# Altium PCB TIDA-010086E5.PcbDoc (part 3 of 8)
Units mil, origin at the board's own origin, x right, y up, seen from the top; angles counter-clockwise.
Board outline 6400 x 6200 mil, 6 copper layers (Top Layer, Power, AGND, Signal, PGND, Bottom Layer), stack 70.536 mil thick; 717 components, 376 nets, 2259 pads, 2183 vias.
Unrouted connection lines stored in the file: 1424.
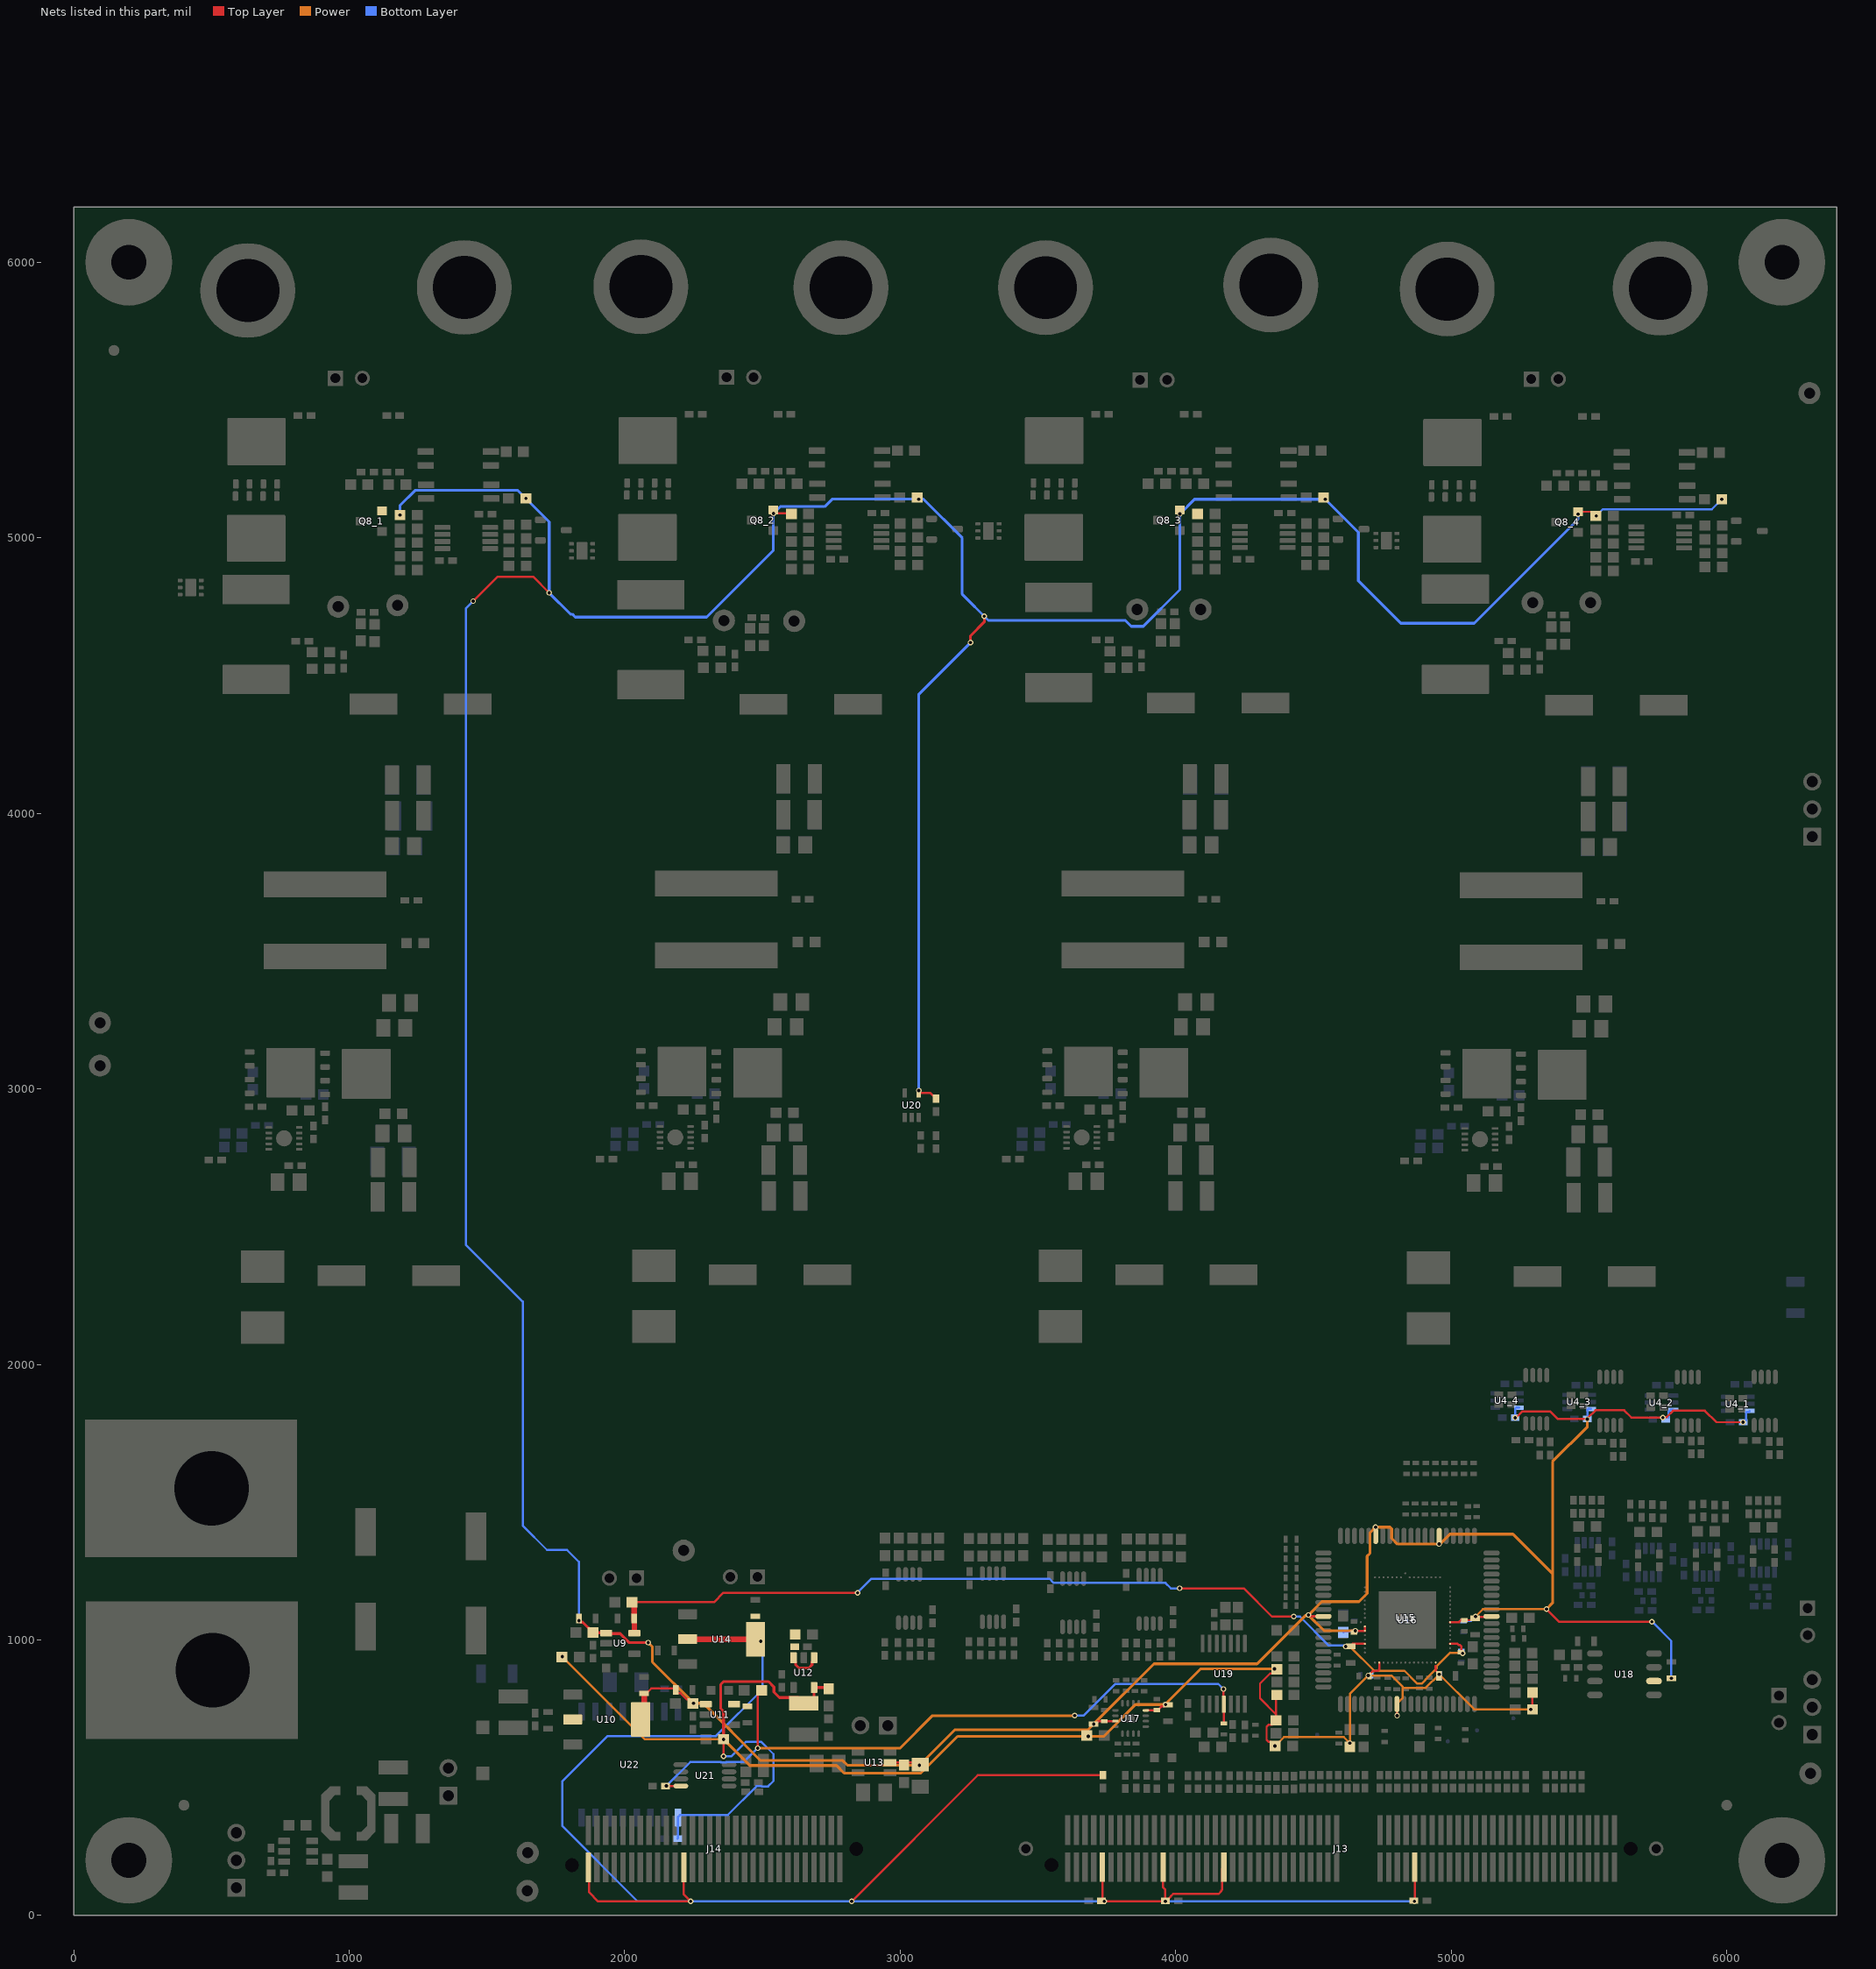
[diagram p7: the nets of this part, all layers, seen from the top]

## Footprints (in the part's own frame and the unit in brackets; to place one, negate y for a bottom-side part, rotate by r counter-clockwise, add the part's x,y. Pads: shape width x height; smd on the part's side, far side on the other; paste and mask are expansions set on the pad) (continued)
RSK0064B-MFG [mm] "Recommended Land Pattern"
  round 0.18 smd paste-1000 mask+0: 1(-3.925,3) 2(-3.925,2.6) 3(-3.925,2.2) 4(-3.935,1.8) 5(-3.935,1.4) 6(-3.925,1) 7(-3.935,0.6) 8(-3.925,0.2) 9(-4.3,-0.2) 10(-3.925,-0.6) 11(-3.925,-1) 12(-3.925,-1.4) 13(-3.925,-1.8) 14(-3.925,-2.2) 15(-3.925,-2.6) 16(-3.925,-3) 17(-3,-3.925) 18(-2.6,-3.925) 19(-2.2,-3.925) 20(-1.8,-3.935) 21(-1.4,-3.935) 22(-1,-3.925) 23(-0.6,-3.935) 24(-0.2,-3.925) 25(0.2,-4.3) 26(0.6,-3.925) 27(1,-3.925) 28(1.4,-3.925) 29(1.8,-3.925) 30(2.2,-3.925) 31(2.6,-3.925) 32(3,-3.925) 33(3.925,-3) 34(3.925,-2.6) 35(3.925,-2.2) 36(3.935,-1.8) 37(3.935,-1.4) 38(3.925,-1) 39(3.935,-0.6) 40(3.925,-0.2) 41(3.935,0.2) 42(3.925,0.6) 43(3.925,1) 44(3.925,1.4) 45(3.925,1.8) 46(3.925,2.2) 47(3.925,2.6) 48(3.925,3) 49(3,3.925) 50(2.6,3.925) 51(2.2,3.925) 52(1.8,3.935) 53(1.4,3.935) 54(1,3.925) 55(0.6,3.935) 56(0.2,3.925) 57(-0.2,3.935) 58(-0.6,3.925) 59(-1,3.925) 60(-1.4,3.925) 61(-1.8,3.925) 62(-2.2,3.925) 63(-2.6,3.925) 64(-3,3.925)
  rrect2% 5.31x5.31 smd paste-1000 mask+0: 65(0,0)
  Top Layer region: -2.9,4.4 -2.9,3.55 -2.913,3.5 -2.95,3.463 -3,3.45 -3,3.45 -3.038,3.458 -3.071,3.479 -3.092,3.512 -3.1,3.55 -3.1,3.55 -3.1,4.4
  Top Layer region: -2.5,4.4 -2.5,3.55 -2.508,3.512 -2.529,3.479 -2.562,3.458 -2.6,3.45 -2.6,3.45 -2.638,3.458 -2.671,3.479 -2.692,3.512 -2.7,3.55 -2.7,3.55 -2.7,4.4
  Top Layer region: -2.1,4.4 -2.1,3.55 -2.113,3.5 -2.15,3.463 -2.2,3.45 -2.2,3.45 -2.238,3.458 -2.271,3.479 -2.292,3.512 -2.3,3.55 -2.3,3.55 -2.3,4.4
  Top Layer region: -1.7,4.4 -1.7,3.55 -1.713,3.5 -1.75,3.463 -1.8,3.45 -1.8,3.45 -1.838,3.458 -1.871,3.479 -1.892,3.512 -1.9,3.55 -1.9,3.55 -1.9,4.4
  Top Layer region: -1.3,4.4 -1.3,3.55 -1.313,3.5 -1.35,3.463 -1.4,3.45 -1.4,3.45 -1.438,3.458 -1.471,3.479 -1.492,3.512 -1.5,3.55 -1.5,3.55 -1.5,4.4
  Top Layer region: -0.9,4.4 -0.9,3.55 -0.908,3.512 -0.929,3.479 -0.962,3.458 -1,3.45 -1,3.45 -1.038,3.458 -1.071,3.479 -1.092,3.512 -1.1,3.55 -1.1,3.55 -1.1,4.4
  Top Layer region: -0.5,4.4 -0.5,3.55 -0.513,3.5 -0.55,3.463 -0.6,3.45 -0.6,3.45 -0.638,3.458 -0.671,3.479 -0.692,3.512 -0.7,3.55 -0.7,3.55 -0.7,4.4
  Top Layer region: -0.1,4.4 -0.1,3.55 -0.108,3.512 -0.129,3.479 -0.162,3.458 -0.2,3.45 -0.2,3.45 -0.238,3.458 -0.271,3.479 -0.292,3.512 -0.3,3.55 -0.3,3.55 -0.3,4.4
  Top Layer region: 0.3,4.4 0.3,3.55 0.292,3.512 0.271,3.479 0.238,3.458 0.2,3.45 0.2,3.45 0.162,3.458 0.129,3.479 0.108,3.512 0.1,3.55 0.1,3.55 0.1,4.4
  Top Layer region: 0.7,4.4 0.7,3.55 0.687,3.5 0.65,3.463 0.6,3.45 0.6,3.45 0.562,3.458 0.529,3.479 0.508,3.512 0.5,3.55 0.5,3.55 0.5,4.4
  Top Layer region: 1.1,4.4 1.1,3.55 1.087,3.5 1.05,3.463 1,3.45 1,3.45 0.962,3.458 0.929,3.479 0.908,3.512 0.9,3.55 0.9,3.55 0.9,4.4
  Top Layer region: 1.5,4.4 1.5,3.55 1.487,3.5 1.45,3.463 1.4,3.45 1.4,3.45 1.362,3.458 1.329,3.479 1.308,3.512 1.3,3.55 1.3,3.55 1.3,4.4
  Top Layer region: 1.9,4.4 1.9,3.55 1.887,3.5 1.85,3.463 1.8,3.45 1.8,3.45 1.762,3.458 1.729,3.479 1.708,3.512 1.7,3.55 1.7,3.55 1.7,4.4
  Top Layer region: 2.3,4.4 2.3,3.55 2.287,3.5 2.25,3.463 2.2,3.45 2.2,3.45 2.162,3.458 2.129,3.479 2.108,3.512 2.1,3.55 2.1,3.55 2.1,4.4
  Top Layer region: 2.7,4.4 2.7,3.55 2.692,3.512 2.671,3.479 2.638,3.458 2.6,3.45 2.6,3.45 2.562,3.458 2.529,3.479 2.508,3.512 2.5,3.55 2.5,3.55 2.5,4.4
  Top Layer region: 3.1,4.4 3.1,3.55 3.087,3.5 3.05,3.463 3,3.45 3,3.45 2.962,3.458 2.929,3.479 2.908,3.512 2.9,3.55 2.9,3.55 2.9,4.4
  Top Layer region: 2.9,-4.4 2.9,-3.55 2.908,-3.512 2.929,-3.479 2.962,-3.458 3,-3.45 3,-3.45 3.038,-3.458 3.071,-3.479 3.092,-3.512 3.1,-3.55 3.1,-3.55 3.1,-4.4
  Top Layer region: 2.5,-4.4 2.5,-3.55 2.508,-3.512 2.529,-3.479 2.562,-3.458 2.6,-3.45 2.6,-3.45 2.638,-3.458 2.671,-3.479 2.692,-3.512 2.7,-3.55 2.7,-3.55 2.7,-4.4
  Top Layer region: 2.1,-4.4 2.1,-3.55 2.108,-3.512 2.129,-3.479 2.162,-3.458 2.2,-3.45 2.2,-3.45 2.238,-3.458 2.271,-3.479 2.292,-3.512 2.3,-3.55 2.3,-3.55 2.3,-4.4
  Top Layer region: 1.7,-4.4 1.7,-3.55 1.708,-3.512 1.729,-3.479 1.762,-3.458 1.8,-3.45 1.8,-3.45 1.838,-3.458 1.871,-3.479 1.892,-3.512 1.9,-3.55 1.9,-3.55 1.9,-4.4
  Top Layer region: 1.3,-4.4 1.3,-3.55 1.308,-3.512 1.329,-3.479 1.362,-3.458 1.4,-3.45 1.4,-3.45 1.438,-3.458 1.471,-3.479 1.492,-3.512 1.5,-3.55 1.5,-3.55 1.5,-4.4
  Top Layer region: 0.9,-4.4 0.9,-3.55 0.908,-3.512 0.929,-3.479 0.962,-3.458 1,-3.45 1,-3.45 1.038,-3.458 1.071,-3.479 1.092,-3.512 1.1,-3.55 1.1,-3.55 1.1,-4.4
  Top Layer region: 0.5,-4.4 0.5,-3.55 0.508,-3.512 0.529,-3.479 0.562,-3.458 0.6,-3.45 0.6,-3.45 0.638,-3.458 0.671,-3.479 0.692,-3.512 0.7,-3.55 0.7,-3.55 0.7,-4.4
  Top Layer region: 0.1,-4.4 0.1,-3.55 0.108,-3.512 0.129,-3.479 0.162,-3.458 0.2,-3.45 0.2,-3.45 0.238,-3.458 0.271,-3.479 0.292,-3.512 0.3,-3.55 0.3,-3.55 0.3,-4.4
  Top Layer region: -0.3,-4.4 -0.3,-3.55 -0.292,-3.512 -0.271,-3.479 -0.238,-3.458 -0.2,-3.45 -0.2,-3.45 -0.162,-3.458 -0.129,-3.479 -0.108,-3.512 -0.1,-3.55 -0.1,-3.55 -0.1,-4.4
  Top Layer region: -0.7,-4.4 -0.7,-3.55 -0.692,-3.512 -0.671,-3.479 -0.638,-3.458 -0.6,-3.45 -0.6,-3.45 -0.562,-3.458 -0.529,-3.479 -0.508,-3.512 -0.5,-3.55 -0.5,-3.55 -0.5,-4.4
  Top Layer region: -1.1,-4.4 -1.1,-3.55 -1.092,-3.512 -1.071,-3.479 -1.038,-3.458 -1,-3.45 -1,-3.45 -0.962,-3.458 -0.929,-3.479 -0.908,-3.512 -0.9,-3.55 -0.9,-3.55 -0.9,-4.4
  Top Layer region: -1.5,-4.4 -1.5,-3.55 -1.492,-3.512 -1.471,-3.479 -1.438,-3.458 -1.4,-3.45 -1.4,-3.45 -1.362,-3.458 -1.329,-3.479 -1.308,-3.512 -1.3,-3.55 -1.3,-3.55 -1.3,-4.4
  Top Layer region: -1.9,-4.4 -1.9,-3.55 -1.892,-3.512 -1.871,-3.479 -1.838,-3.458 -1.8,-3.45 -1.8,-3.45 -1.762,-3.458 -1.729,-3.479 -1.708,-3.512 -1.7,-3.55 -1.7,-3.55 -1.7,-4.4
  Top Layer region: -2.3,-4.4 -2.3,-3.55 -2.292,-3.512 -2.271,-3.479 -2.238,-3.458 -2.2,-3.45 -2.2,-3.45 -2.162,-3.458 -2.129,-3.479 -2.108,-3.512 -2.1,-3.55 -2.1,-3.55 -2.1,-4.4
  Top Layer region: -2.7,-4.4 -2.7,-3.55 -2.692,-3.512 -2.671,-3.479 -2.638,-3.458 -2.6,-3.45 -2.6,-3.45 -2.562,-3.458 -2.529,-3.479 -2.508,-3.512 -2.5,-3.55 -2.5,-3.55 -2.5,-4.4
  Top Layer region: -3.1,-4.4 -3.1,-3.55 -3.092,-3.512 -3.071,-3.479 -3.038,-3.458 -3,-3.45 -3,-3.45 -2.962,-3.458 -2.929,-3.479 -2.908,-3.512 -2.9,-3.55 -2.9,-3.55 -2.9,-4.4
  Top Layer region: 4.4,2.9 3.55,2.9 3.512,2.908 3.479,2.929 3.458,2.962 3.45,3 3.45,3 3.458,3.038 3.479,3.071 3.512,3.092 3.55,3.1 3.55,3.1 4.4,3.1
  Top Layer region: 4.4,2.5 3.55,2.5 3.512,2.508 3.479,2.529 3.458,2.562 3.45,2.6 3.45,2.6 3.458,2.638 3.479,2.671 3.512,2.692 3.55,2.7 3.55,2.7 4.4,2.7
  Top Layer region: 4.4,2.1 3.55,2.1 3.512,2.108 3.479,2.129 3.458,2.162 3.45,2.2 3.45,2.2 3.458,2.238 3.479,2.271 3.512,2.292 3.55,2.3 3.55,2.3 4.4,2.3
  Top Layer region: 4.4,1.7 3.55,1.7 3.512,1.708 3.479,1.729 3.458,1.762 3.45,1.8 3.45,1.8 3.458,1.838 3.479,1.871 3.512,1.892 3.55,1.9 3.55,1.9 4.4,1.9
  Top Layer region: 4.4,1.3 3.55,1.3 3.512,1.308 3.479,1.329 3.458,1.362 3.45,1.4 3.45,1.4 3.458,1.438 3.479,1.471 3.512,1.492 3.55,1.5 3.55,1.5 4.4,1.5
  Top Layer region: 4.4,0.9 3.55,0.9 3.512,0.908 3.479,0.929 3.458,0.962 3.45,1 3.45,1 3.458,1.038 3.479,1.071 3.512,1.092 3.55,1.1 3.55,1.1 4.4,1.1
  Top Layer region: 4.4,0.5 3.55,0.5 3.512,0.508 3.479,0.529 3.458,0.562 3.45,0.6 3.45,0.6 3.458,0.638 3.479,0.671 3.512,0.692 3.55,0.7 3.55,0.7 4.4,0.7
  Top Layer region: 4.4,0.1 3.55,0.1 3.512,0.108 3.479,0.129 3.458,0.162 3.45,0.2 3.45,0.2 3.458,0.238 3.479,0.271 3.512,0.292 3.55,0.3 3.55,0.3 4.4,0.3
  Top Layer region: 4.4,-0.3 3.55,-0.3 3.512,-0.292 3.479,-0.271 3.458,-0.238 3.45,-0.2 3.45,-0.2 3.458,-0.162 3.479,-0.129 3.512,-0.108 3.55,-0.1 3.55,-0.1 4.4,-0.1
  Top Layer region: 4.4,-0.7 3.55,-0.7 3.512,-0.692 3.479,-0.671 3.458,-0.638 3.45,-0.6 3.45,-0.6 3.458,-0.562 3.479,-0.529 3.512,-0.508 3.55,-0.5 3.55,-0.5 4.4,-0.5
  Top Layer region: 4.4,-1.1 3.55,-1.1 3.512,-1.092 3.479,-1.071 3.458,-1.038 3.45,-1 3.45,-1 3.458,-0.962 3.479,-0.929 3.512,-0.908 3.55,-0.9 3.55,-0.9 4.4,-0.9
  Top Layer region: 4.4,-1.5 3.55,-1.5 3.512,-1.492 3.479,-1.471 3.458,-1.438 3.45,-1.4 3.45,-1.4 3.458,-1.362 3.479,-1.329 3.512,-1.308 3.55,-1.3 3.55,-1.3 4.4,-1.3
  Top Layer region: 4.4,-1.9 3.55,-1.9 3.512,-1.892 3.479,-1.871 3.458,-1.838 3.45,-1.8 3.45,-1.8 3.458,-1.762 3.479,-1.729 3.512,-1.708 3.55,-1.7 3.55,-1.7 4.4,-1.7
  Top Layer region: 4.4,-2.3 3.55,-2.3 3.512,-2.292 3.479,-2.271 3.458,-2.238 3.45,-2.2 3.45,-2.2 3.458,-2.162 3.479,-2.129 3.512,-2.108 3.55,-2.1 3.55,-2.1 4.4,-2.1
  Top Layer region: 4.4,-2.7 3.55,-2.7 3.512,-2.692 3.479,-2.671 3.458,-2.638 3.45,-2.6 3.45,-2.6 3.458,-2.562 3.479,-2.529 3.512,-2.508 3.55,-2.5 3.55,-2.5 4.4,-2.5
  Top Layer region: 4.4,-3.1 3.55,-3.1 3.512,-3.092 3.479,-3.071 3.458,-3.038 3.45,-3 3.45,-3 3.458,-2.962 3.479,-2.929 3.512,-2.908 3.55,-2.9 3.55,-2.9 4.4,-2.9
  Top Layer region: -4.4,-2.9 -3.55,-2.9 -3.512,-2.908 -3.479,-2.929 -3.458,-2.962 -3.45,-3 -3.45,-3 -3.463,-3.05 -3.5,-3.087 -3.55,-3.1 -3.55,-3.1 -4.4,-3.1
  Top Layer region: -4.4,-2.5 -3.55,-2.5 -3.512,-2.508 -3.479,-2.529 -3.458,-2.562 -3.45,-2.6 -3.45,-2.6 -3.458,-2.638 -3.479,-2.671 -3.512,-2.692 -3.55,-2.7 -3.55,-2.7 -4.4,-2.7
  Top Layer region: -4.4,-2.1 -3.55,-2.1 -3.512,-2.108 -3.479,-2.129 -3.458,-2.162 -3.45,-2.2 -3.45,-2.2 -3.458,-2.238 -3.479,-2.271 -3.512,-2.292 -3.55,-2.3 -3.55,-2.3 -4.4,-2.3
  Top Layer region: -4.4,-1.7 -3.55,-1.7 -3.512,-1.708 -3.479,-1.729 -3.458,-1.762 -3.45,-1.8 -3.45,-1.8 -3.463,-1.85 -3.5,-1.887 -3.55,-1.9 -3.55,-1.9 -4.4,-1.9
  Top Layer region: -4.4,-1.3 -3.55,-1.3 -3.512,-1.308 -3.479,-1.329 -3.458,-1.362 -3.45,-1.4 -3.45,-1.4 -3.458,-1.438 -3.479,-1.471 -3.512,-1.492 -3.55,-1.5 -3.55,-1.5 -4.4,-1.5
  Top Layer region: -4.4,-0.9 -3.55,-0.9 -3.512,-0.908 -3.479,-0.929 -3.458,-0.962 -3.45,-1 -3.45,-1 -3.458,-1.038 -3.479,-1.071 -3.512,-1.092 -3.55,-1.1 -3.55,-1.1 -4.4,-1.1
  Top Layer region: -4.4,-0.5 -3.55,-0.5 -3.512,-0.508 -3.479,-0.529 -3.458,-0.562 -3.45,-0.6 -3.45,-0.6 -3.458,-0.638 -3.479,-0.671 -3.512,-0.692 -3.55,-0.7 -3.55,-0.7 -4.4,-0.7
  Top Layer region: -4.4,-0.1 -3.55,-0.1 -3.512,-0.108 -3.479,-0.129 -3.458,-0.162 -3.45,-0.2 -3.45,-0.2 -3.458,-0.238 -3.479,-0.271 -3.512,-0.292 -3.55,-0.3 -3.55,-0.3 -4.4,-0.3
  Top Layer region: -4.4,0.3 -3.55,0.3 -3.512,0.292 -3.479,0.271 -3.458,0.238 -3.45,0.2 -3.45,0.2 -3.458,0.162 -3.479,0.129 -3.512,0.108 -3.55,0.1 -3.55,0.1 -4.4,0.1
  Top Layer region: -4.4,0.7 -3.55,0.7 -3.512,0.692 -3.479,0.671 -3.458,0.638 -3.45,0.6 -3.45,0.6 -3.458,0.562 -3.479,0.529 -3.512,0.508 -3.55,0.5 -3.55,0.5 -4.4,0.5
  Top Layer region: -4.4,1.1 -3.55,1.1 -3.512,1.092 -3.479,1.071 -3.458,1.038 -3.45,1 -3.45,1 -3.458,0.962 -3.479,0.929 -3.512,0.908 -3.55,0.9 -3.55,0.9 -4.4,0.9
  Top Layer region: -4.4,1.5 -3.55,1.5 -3.512,1.492 -3.479,1.471 -3.458,1.438 -3.45,1.4 -3.45,1.4 -3.458,1.362 -3.479,1.329 -3.512,1.308 -3.55,1.3 -3.55,1.3 -4.4,1.3
  Top Layer region: -4.4,1.9 -3.55,1.9 -3.512,1.892 -3.479,1.871 -3.458,1.838 -3.45,1.8 -3.45,1.8 -3.458,1.762 -3.479,1.729 -3.512,1.708 -3.55,1.7 -3.55,1.7 -4.4,1.7
  Top Layer region: -4.4,2.3 -3.55,2.3 -3.512,2.292 -3.479,2.271 -3.458,2.238 -3.45,2.2 -3.45,2.2 -3.463,2.15 -3.5,2.113 -3.55,2.1 -3.55,2.1 -4.4,2.1
  Top Layer region: -4.4,2.7 -3.55,2.7 -3.512,2.692 -3.479,2.671 -3.458,2.638 -3.45,2.6 -3.45,2.6 -3.463,2.55 -3.5,2.513 -3.55,2.5 -3.55,2.5 -4.4,2.5
  Top Layer region: -4.4,3.1 -3.55,3.1 -3.512,3.092 -3.479,3.071 -3.458,3.038 -3.45,3 -3.45,3 -3.463,2.95 -3.5,2.913 -3.55,2.9 -3.55,2.9 -4.4,2.9
  silkscreen extent -4.62,-4.08 4.08,4.08, body extent -4.5,-4.5 4.5,4.5, height 0.25
RTE0016D [mm] "QFN, 16-Leads, Body 3x3mm, Pitch 0.5mm"
  oval 0.6x0.24 smd: 1(-1.4,0.75) 2(-1.4,0.25) 3(-1.4,-0.25) 4(-1.4,-0.75) 9(1.4,-0.75) 10(1.4,-0.25) 11(1.4,0.25) 12(1.4,0.75)
  oval 0.24x0.6 smd: 5(-0.75,-1.4) 6(-0.25,-1.4) 7(0.25,-1.4) 8(0.75,-1.4) 13(0.75,1.4) 14(0.25,1.4) 15(-0.25,1.4) 16(-0.75,1.4)
  rect 0.8x0.8 smd paste-0.85: 17(0,0)
  silkscreen extent -1.72,-1.73 1.72,1.73, body extent -1.57,-1.57 1.58,1.58, height 0.81
Samtec_HTSW-102-07-G-S [mm] "Samtec 100mil, 1x2, 230 mil above insulator"
  rrect6% 1.65x1.65 hole 1.016: 1(-1.27,0)
  round 1.65 hole 1.016: 2(1.27,0)
  silkscreen extent -3.3,-1.27 2.54,1.27, body extent -2.54,-1.27 2.54,1.27, height 8.38
Samtec_HTSW-103-07-G-S [mm] "Samtec 100mil, 1x3, 230 mil above insulator"
  rrect6% 1.65x1.65 hole 1.016: 1(-2.54,0)
  round 1.65 hole 1.016: 2(0,0) 3(2.54,0)
  silkscreen extent -4.57,-1.27 3.81,1.27, body extent -3.81,-1.27 3.81,1.27, height 8.38
SOT-23 [mm] "SOT23, 3-Leads, Body 2.9x1.3mm, Pitch 0.95mm, Lead Span 2.5mm, IPC Medium Density"
  rrect50% 1x0.6 smd: 1(-1.2,0.95) 2(-1.2,-0.95) 3(1.2,0)
  silkscreen extent -1.62,-1.5 0.7,1.5, body extent -1.16,-1.45 1.21,1.45, height 1
TI_Stacked_Overlay_Small [mil]
  silkscreen extent -418,-98 418,98
TP_SM_1MM [mil] "1mm Test Point, SMT"
  round 15 smd paste-19.68: 1(0,0)
WEEE_Minimum [mil] "WEEElie bin"
  silkscreen extent -95,-172 99,104
WL-SMCW_GREEN [mm] "WURTH"
  rect 0.8x0.8 smd: 1(-0.8,0) 2(0.8,0)
  silkscreen extent -1.9,-0.8 1.2,0.8, body extent -0.85,-0.45 0.85,0.45, height 0.8
Wurth_60900213421 [mil] "Shunt, 2.54mm, Black"
  round 1 on Mech3: 0(0,0)
  body extent -98,-48 98,48, height 338
XAL1010 [mm] "COILCRAFT"
  rect 2.38x11.31 smd: 1(-3.325,0) 2(3.325,0)
  silkscreen extent -5.3,-6 5.3,6, body extent -5.25,-5.9 5.25,5.9, height 10

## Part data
C1 C2 C9_1 C9_2 C9_3 C9_4 C10_1 C10_2 C10_3 C10_4: library part CMP-0012120-3, "CAP ALUM POLY 150UF 20% 50V SMD", Cap_Case=F12, Manufacturer=Panasonic, Tolerance_%=20%, Value1="0.024 ohm", Value2=50, ValueDisplayed=150uF
C3_1 C3_2 C3_3 C3_4 C4_1 C4_2 C4_3 C4_4 C12_1 C12_2 C12_3 C12_4 C18_1 C18_2 C18_3 C18_4 C41 C42 C43 C48 C59: library part CMP-0085817-1, "CAP, CERM, 22 µF, 35 V,+/- 20%, X5R, 1210", Cap_Case=1210, Manufacturer="Taiyo Yuden", TempCo=X5R, Tolerance_%=20%, Value2=35V, ValueDisplayed=22µF
C5_1 C5_2 C5_3 C5_4 C7_1 C7_2 C7_3 C7_4 C13_1 C13_2 C13_3 C13_4 C15_1 C15_2 C15_3 C15_4 C57 C62 C63: library part CMP-0008350-2, "CAP, CERM, 1 uF, 50 V, +/- 10%, X7R, 0805", Cap_Case=0805, Manufacturer=MuRata, Supplier Part Number 1=490-4736-1-ND, TempCo=X7R, Tolerance_%=10%, Value1=Unknown, Value2=50V, ValueDisplayed=1uF
C6_1 C6_2 C6_3 C6_4 C14_1 C14_2 C14_3 C14_4 C40 C44: library part CMP-0007469-4, "CAP, CERM, 0.1 uF, 100 V, +/- 10%, X7R, 0603", Cap_Case=0603, Manufacturer=MuRata, Supplier Part Number 1=490-3285-1-ND, TempCo=X7R, Tolerance_%=10%, Value1=Unknown, Value2=100V, ValueDisplayed=0.1uF
C8_1 C8_2 C8_3 C8_4 C11_1 C11_2 C11_3 C11_4 C16_1 C16_2 C16_3 C16_4 C17_1 C17_2 C17_3 C17_4: library part CMP-0009201-2, "CAP, CERM, 47 uF, 16 V, +/- 20%, X6S, 1210", Cap_Case=1210, Manufacturer=MuRata, Supplier Part Number 1=490-9968-1-ND, TempCo=X6S, Tolerance_%=20%, Value1=Unknown, Value2=16V, ValueDisplayed=47uF
C19_1 C19_2 C19_3 C19_4: library part CMP-0008093-2, "CAP, CERM, 100 pF, 100 V, +/- 5%, C0G/NP0, 0805", Cap_Case=0805, Manufacturer=MuRata, Supplier Part Number 1=490-1599-1-ND, TempCo=C0G/NP0, Tolerance_%=5%, Value1=Unknown, Value2=100V, ValueDisplayed=100pF
C20_1 C20_2 C20_3 C20_4 C61 C102: library part CMP-0006644-2, "CAP, CERM, 0.015 uF, 16 V, +/- 10%, X7R, 0402", Cap_Case=0402, Manufacturer=MuRata, Supplier Part Number 1=490-1314-1-ND, TempCo=X7R, Tolerance_%=10%, Value1=Unknown, Value2=16V, ValueDisplayed=0.015uF
C21_1 C21_2 C21_3 C21_4: library part CMP-0008309-2, "CAP, CERM, 4.7 uF, 50 V, +/- 10%, X5R, 0805", Cap_Case=0805, Manufacturer=MuRata, Supplier Part Number 1=GRM21BR61H475KE51L-ND, TempCo=X5R, Tolerance_%=10%, Value1=Unknown, Value2=50V, ValueDisplayed=4.7uF
C22_1 C22_2 C22_3 C22_4 C23_1 C23_2 C23_3 C23_4 C25_1 C25_2 C25_3 C25_4 C26_1 C26_2 C26_3 C26_4 C27_1 C27_2 C27_3 C27_4 C29_1 C29_2 C29_3 C29_4 C30_1 C30_2 C30_3 C30_4 C33_1 C33_2 C33_3 C33_4 C34_1 C34_2 C34_3 C34_4 C36_1 C36_2 C36_3 C36_4 C38_1 C38_2 C38_3 C38_4 C39_1 C39_2 C39_3 C39_4 C45 C53 C54 C56 C64 C65 C69 C70 C71 C72 C75 C76 C83 C84 C89 C92 C99 C100 C101 C103 C104 C105 C106 C107_1 C107_2 C107_3 C107_4: library part CMP-0006591-2, "CAP, CERM, 0.1 uF, 16 V, +/- 10%, X5R, 0402", Cap_Case=0402, Manufacturer=MuRata, Supplier Part Number 1=490-5415-1-ND, TempCo=X5R, Tolerance_%=10%, Value1=Unknown, Value2=16V, ValueDisplayed=0.1uF
C24_1 C24_2 C24_3 C24_4: library part CMP-0007445-4, "CAP, CERM, 0.22 uF, 50 V, +/- 10%, X7R, 0603", Cap_Case=0603, Manufacturer=MuRata, Supplier Part Number 1=490-12546-1-ND, TempCo=X7R, Tolerance_%=10%, Value1=Unknown, Value2=50V, ValueDisplayed=0.22uF
C28_1 C28_2 C28_3 C28_4 C32_1 C32_2 C32_3 C32_4: library part CMP-0006412-2, "CAP, CERM, 1000 pF, 50 V, +/- 5%, C0G/NP0, 0402", Cap_Case=0402, Manufacturer=MuRata, Supplier Part Number 1=490-3244-1-ND, TempCo=C0G/NP0, Tolerance_%=5%, Value1=Unknown, Value2=50V, ValueDisplayed=1000pF
C31_1 C31_2 C31_3 C31_4: library part CMP-0007210-4, "CAP, CERM, 3300 pF, 50 V, +/- 5%, C0G/NP0, 0603", Cap_Case=0603, Manufacturer=MuRata, Supplier Part Number 1=GRM1885C1H332JA01D-ND, TempCo=C0G/NP0, Tolerance_%=5%, Value1=Unknown, Value2=50V, ValueDisplayed=3300pF
C35_1 C35_2 C35_3 C35_4: library part CMP-0006611-2, "CAP, CERM, 4700 pF, 25 V, +/- 10%, X5R, 0402", Cap_Case=0402, Manufacturer=MuRata, Supplier Part Number 1=GRM155R61E472KA01D-ND, TempCo=X5R, Tolerance_%=10%, Value1=Unknown, Value2=25V, ValueDisplayed=4700pF
C37_1 C37_2 C37_3 C37_4: library part CMP-0007479-4, "CAP, CERM, 3300 pF, 100 V, +/- 10%, X7R, 0603", Cap_Case=0603, Manufacturer=MuRata, Supplier Part Number 1=490-1481-1-ND, TempCo=X7R, Tolerance_%=10%, Value1=Unknown, Value2=100V, ValueDisplayed=3300pF
C46 C47 C50 C51 C52 C60 C66 C68 C73 C74 C82 C85 C86 C87: library part CMP-0076705-3, "CAP, CERM, 1 µF, 25 V,+/- 10%, X7R, AEC-Q200 Grade 1, 0603", Cap_Case=1.6x0.8x0.8mm, Manufacturer=TDK, Supplier Part Number 1=445-6931-1-ND, TempCo=X7R, Tolerance_%=10%, Value2=25V, ValueDisplayed=1µF
C49 C58: library part CMP-0076705-3, "CAP TANT POLY 2.2UF 10V 0603", Cap_Case=1.6x0.8x0.8mm, Manufacturer="KYOCERA AVX", TempCo=X7R, Tolerance_%=20%, Value2=10V, ValueDisplayed=2.2uF
C55 C67 C77 C80 C81 C90: library part CMP-0007344-5, "CAP, CERM, 10 uF, 25 V, +/- 20%, X5R, 0603", Cap_Case=0603, Manufacturer=MuRata, Supplier Part Number 1=490-7202-1-ND, TempCo=X5R, Tolerance_%=20%, Value1=Unknown, Value2=25V, ValueDisplayed=10uF
C78 C79: library part CMP-0064936-4, "CAP, CERM, 4.7 uF, 16 V,+/- 10%, X7R, 0603", Cap_Case=0603, Manufacturer=MuRata, TempCo=X7R, Tolerance_%=10%, Value1=Unknown, Value2=16V, ValueDisplayed=4.7uF
C88 C91 C108_1 C108_2 C108_3 C108_4: library part CMP-0006640-1, "CAP, CERM, 0.1 uF, 16 V, +/- 5%, X7R, 0402", Cap_Case=0402, Manufacturer=MuRata, Supplier Part Number 1=490-6327-1-ND, TempCo=X7R, Tolerance_%=5%, Value1=Unknown, Value2=16V, ValueDisplayed=0.1uF
C93: library part CMP-0078265-1, "CAP, CERM, 0.22 µF, 16 V,+/- 10%, X7R, AEC-Q200 Grade 1, 0402", Cap_Case=0402, Manufacturer=MuRata, Supplier Part Number 1=490-10671-1-ND, TempCo=X7R, Tolerance_%=10%, Value2=16V, ValueDisplayed=0.22µF
C94 C95 C96 C97 C98: library part CMP-0006639-2, "CAP, CERM, 0.01 uF, 16 V, +/- 10%, X7R, 0402", Cap_Case=0402, Manufacturer=MuRata, Supplier Part Number 1=490-1313-1-ND, TempCo=X7R, Tolerance_%=10%, Value1=Unknown, Value2=16V, ValueDisplayed=0.01uF
D1 D2 D3 D4: library part CMP-0002894-2, "LED, Green, SMD", Color=green, Manufacturer="Wurth Elektronik", Value1=W, Value2=2V
F1_1 F1_2 F1_3 F1_4: library part CMP-0003569-2, "Fuse, 15 A, SMD", Irating_A=15A
FID1 FID2 FID3: library part CMP-0077181-1, "Fiducial mark.  There is nothing to buy or mount.", Manufacturer=N/A
H1 H2 H3 H4: library part CMP-0003617-1, "Machine Screw, Round, #4-40 x 1/4, Nylon, Philips panhead", Manufacturer="B&F Fastener Supply", Supplier Part Number 1=H542-ND
H5 H6 H7 H8: library part CMP-0003610-1, "Standoff, Hex, 0.5\"L #4-40 Nylon", Manufacturer=Keystone, Supplier Part Number 1=36-1902C-ND
J1 J2: library part CMP-0055387-2, "Standard Banana Jack, Uninsulated, 15A", Manufacturer="Cinch Connectivity", Supplier Part Number 1=J147-ND
J3 J4 J8_1 J8_2 J8_3 J8_4 J15 J16: library part CMP-0075228-1, "Header (Shrouded), 2.5mm, 2x1, Tin, TH", Color=White, Current_A=3A, Manufacturer="JST Manufacturing", Supplier Part Number 1=455-1611-ND, Voltage_V=250V
J5 J6 J11: library part CMP-0075484-1, "Header, 100mil, 3x1, Gold, TH", Manufacturer=Samtec, Supplier Part Number 1=HTSW-103-07-G-S-ND
J7_1 J7_2 J7_3 J7_4 J9_1 J9_2 J9_3 J9_4: library part CMP-0001389-1, "Terminal Connector Rectangular Lug, Grounding 6-14 AWG 3/16 Stud", Digikey Part Number=298-11610-ND, Manufacturer=Panduit, Mouser Part Number=644-CXS35-36T-C, Operating Temperature Range=to, Voltage_V=600V
J10 J12: library part CMP-0075483-1, "Header, 100mil, 2x1, Gold, TH", Manufacturer=Samtec, Supplier Part Number 1=SAM8736-ND
J13: library part CMP-0003814-2, "C2000 controlCARD-120HSEC connector, SMT", Manufacturer=Samtec
J14: library part CMP-0003859-2, "C2000 controlCARD-180HSEC (60-pin addon) connector, SMT", Manufacturer=Samtec
L1_1 L1_2 L1_3 L1_4: library part CMP-0060950-1, "Inductor, Shielded, Composite, 4.7 uH, 24 A, 0.01 ohm, SMD", Manufacturer=Coilcraft, Supplier Part Number 1=994-XAL1010-472MEB, Value1="0.01 ohm", Value2=24A, ValueDisplayed=4.7uH
L2: library part CMP-0061372-2, "Inductor, Shielded Drum Core, Ferrite, 18 uH, 0.8 A, 0.55 ohm, SMD", Manufacturer=Coilcraft, Value1="0.55 ohm", Value2=0.8A, ValueDisplayed=18uH
L3: library part CMP-0003369-1, "Ferrite Bead, 1000 ohm @ 100 MHz, 1.5 A, 1806", Manufacturer=MuRata, Supplier Part Number 1=490-1061-1-ND, Value1="0.09 ohm", Value2=1.5A, ValueDisplayed="1000 ohm"
LBL1: library part CMP-0003625-1, "Thermal Transfer Printable Labels, 0.650\" W x 0.200\" H - 10,000 per roll", Manufacturer=Brady, Supplier Part Number 1=97C5133
Logo1: library part CMP-0074844-1
Logo2: library part CMP-0074838-1, "Texas Instrument Corporate Signature"
Logo3: library part CMP-0074847-1, "FCC_disclaimer"
Logo4: library part CMP-0074769-3, Manufacturer="Texas Instruments"
Logo5 Logo6: library part CMP-0074837-2, "IEC 61010-1 Hot Surface Warning", Manufacturer="Texas Instruments"
Q1_1 Q1_2 Q1_3 Q1_4 Q4_1 Q4_2 Q4_3 Q4_4: library part CMP-0000572-1, "MOSFET, N-CH, 30 V, 100 A, DQJ0008A (VSONP-8)", Alternate Manufacturer=None, Manufacturer="Texas Instruments", Supplier Part Number 1=296-28437-1-ND, Value1=0, Value2="13.2 nC"
Q2_1 Q2_2 Q2_3 Q2_4 Q3_1 Q3_2 Q3_3 Q3_4: library part CMP-0000586-2, "MOSFET, N-CH, 30 V, 100 A, DNK0008A (VSON-CLIP-8)", Alternate Manufacturer=None, Manufacturer="Texas Instruments", Supplier Part Number 1=CSD17573Q5B-ND, Value1=0.0014, Value2="49 nC"
Q5_1 Q5_2 Q5_3 Q5_4 Q7_1 Q7_2 Q7_3 Q7_4: library part CMP-0120549-1, "3.75-kVRMS, Single-Channel Opto-Emulator with Analog Transistor Output", Emiiter Collector Voltage=7V, Forward Current=5mA, Manufacturer="Texas Instruments", Operating Temperature Range="-55°C to +125°C", Power_TotalModule=200mW, Voltage_Isolation_Vrms=3750Vrms
Q6_1 Q6_2 Q6_3 Q6_4: library part CMP-0085603-1, "MOSFET, N-CH, 60 V, 0.115 A, AEC-Q101, SOT-23", Alternate Manufacturer=None, Manufacturer="Diodes Inc.", Value1="? ohm", Value2="0.223 nC"
Q8_1 Q8_2 Q8_3 Q8_4: library part CMP-0090761-1, "P-Channel 50V 130mA (Ta) 225mW (Ta) Surface Mount SOT-23-3 (TO-236)", Digikey Part Number=BSS84LT1GOSCT-ND, Drain To Source Breakdown Voltage=-50V, Input Capacitace At Vds="36pF @ 5V", Manufacturer="On Semiconductor", Mouser Part Number=863-BSS84LT1G, Operating Temperature Range="-55°C to +150°C", Power_W=225mW, Pulse Drain Current=-520mA
R1_1 R1_2 R1_3 R1_4: library part CMP-0042997-1, "2 mOhms ±1% 6W Chip Resistor 3920 (1052 Metric) Automotive AEC-Q200, Current Sense Metal Element", Digikey Part Number=4506-SEWF3920F2L00P9CT-ND, Manufacturer=RESI, Operating Temperature Range="-65°C to +170°C", Power_W=6W, TempCo=25ppm/°C, Tolerance_%=1%
R2_1 R2_2 R2_3 R2_4 R7_1 R7_2 R7_3 R7_4 R20_1 R20_2 R20_3 R20_4 R21_1 R21_2 R21_3 R21_4 R28_1 R28_2 R28_3 R28_4 R47_1 R47_2 R47_3 R47_4 R50_1 R50_2 R50_3 R50_4 R59 R60 R157: library part CMP-0022447-4, "RES, 49.9 k, 1%, 0.1 W, AEC-Q200 Grade 0, 0603", Manufacturer=Vishay-Dale, Power_W=100mW, Supplier Part Number 1=541-49.9KHCT-ND, TempCo="100 ppm/C", Tolerance_%=1%, Value2=0.1W, Value_Code=49k9, ValueDisplayed=49.9k
R3_1 R3_2 R3_3 R3_4: library part CMP-0020448-3, "RES, 10, 5%, 0.125 W, AEC-Q200 Grade 0, 0805", Manufacturer=Vishay-Dale, Power_W=125mW, Supplier Part Number 1=541-10ACT-ND, TempCo="200 ppm/C", Tolerance_%=5%, Value2=0.125W, Value_Code=10R0, ValueDisplayed=10
R4_1 R4_2 R4_3 R4_4 R5_1 R5_2 R5_3 R5_4: library part CMP-0022170-4, "RES, 1.00, 1%, 0.1 W, AEC-Q200 Grade 0, 0603", Manufacturer=Vishay-Dale, Power_W=100mW, Supplier Part Number 1=52K8059, TempCo="100 ppm/C", Tolerance_%=1%, Value2=0.1W, Value_Code=1R00, ValueDisplayed=1.00
R6_1 R6_2 R6_3 R6_4 R8_1 R8_2 R8_3 R8_4 R9_1 R9_2 R9_3 R9_4 R10_1 R10_2 R10_3 R10_4 R11_1 R11_2 R11_3 R11_4 R17_1 R17_2 R17_3 R17_4 R27_1 R27_2 R27_3 R27_4 R31_1 R31_2 R31_3 R31_4 R32_1 R32_2 R32_3 R32_4 R33_1 R33_2 R33_3 R33_4 R35_1 R35_2 R35_3 R35_4 R39_1 R39_2 R39_3 R39_4 R40_1 R40_2 R40_3 R40_4 R41_1 R41_2 R41_3 R41_4 R43 R49_1 R49_2 R49_3 R49_4 R65 R66 R67 R68 R71 R72 R73 R74 R75 R76 R77 R78 R79 R87 R88 R89 R94 R95 R96 R97 R99 R100 R101 R102 R103 R104 R105 R106 R107 R109 R117 R123 R124 R126 R127 R128 R129 R131 R133 R138 R139 R165 R166 R167 R168 R169 R170 R171 R172 R173 R174 R175 R176 R177 R178 R179: library part CMP-0026822-3, "RES, 0, 5%, 0.063 W, AEC-Q200 Grade 0, 0402", Manufacturer=Vishay-Dale, Power_W=63mW, Supplier Part Number 1=541-0.0JCT-ND, TempCo="200 ppm/C", Tolerance_%=5%, Value2=0.063W, Value_Code=0000, ValueDisplayed=0
R12_1 R12_2 R12_3 R12_4 R13_1 R13_2 R13_3 R13_4 R15_1 R15_2 R15_3 R15_4 R19_1 R19_2 R19_3 R19_4 R23_1 R23_2 R23_3 R23_4 R24_1 R24_2 R24_3 R24_4 R25_1 R25_2 R25_3 R25_4 R42_1 R42_2 R42_3 R42_4 R61 R62 R69 R70 R80 R81 R82 R83 R84 R85 R86 R90 R91 R92 R93 R98 R108 R110 R114 R116: library part CMP-0021998-4, "RES, 10.0 k, 1%, 0.1 W, AEC-Q200 Grade 0, 0603", Manufacturer=Vishay-Dale, Power_W=100mW, Supplier Part Number 1=541-10.0KHCT-ND, TempCo="100 ppm/C", Tolerance_%=1%, Value2=0.1W, Value_Code=10k0, ValueDisplayed=10.0k
R14_1 R14_2 R14_3 R14_4 R18_1 R18_2 R18_3 R18_4 R29_1 R29_2 R29_3 R29_4 R57 R58 R63 R64: library part CMP-0025729-4, "RES, 1.0 k, 5%, 0.1 W, AEC-Q200 Grade 0, 0603", Manufacturer=Vishay-Dale, Power_W=100mW, Supplier Part Number 1=541-1.0KGCT-ND, TempCo="200 ppm/C", Tolerance_%=5%, Value2=0.1W, Value_Code=1k00, ValueDisplayed=1.0k
R16_1 R16_2 R16_3 R16_4 R22_1 R22_2 R22_3 R22_4 R26_1 R26_2 R26_3 R26_4 R30_1 R30_2 R30_3 R30_4 R156: library part CMP-0082533-1, "RES, 4.99 k, 1%, 0.1 W, 0603", Manufacturer=Vishay-Dale, Power_W=100mW, Supplier Part Number 1=541-3985-1-ND, TempCo="100 ppm/C", Tolerance_%=1%, Value2=0.1W, Value_Code=4k99, ValueDisplayed=4.99k
R34_1 R34_2 R34_3 R34_4 R37_1 R37_2 R37_3 R37_4 R111 R115: library part CMP-0026402-2, "RES, 499, 1%, 0.063 W, AEC-Q200 Grade 0, 0402", Manufacturer=Vishay-Dale, Power_W=63mW, Supplier Part Number 1=541-499LCT-ND, TempCo="100 ppm/C", Tolerance_%=1%, Value2=0.063W, Value_Code=499R, ValueDisplayed=499
R36_1 R36_2 R36_3 R36_4: library part CMP-0065358-1, "RES, 20.0 k, .1%, .0625 W, 0402", Manufacturer="Yageo America", Power_W=62.5mW, Supplier Part Number 1=YAG1388CT-ND, TempCo="25 ppm/C", Tolerance_%=0.1%, Value1=.1%, Value2=.0625W, Value_Code=20k0, ValueDisplayed=20.0k
R38_1 R38_2 R38_3 R38_4: library part CMP-0092050-1, "Res Thin Film 0402 100 Ohm 0.1% 0.063W(1/16W) ±25ppm/C Pad SMD T/R", Digikey Part Number=YAG2301CT-ND, Manufacturer=Yageo, Mouser Part Number=603-RT0402BRD07100RL, Operating Temperature Range="-55°C to +155°C", Power_W=63mW, TempCo=25ppm/°C, Tolerance_%=0.1%
R44_1 R44_2 R44_3 R44_4 R51_1 R51_2 R51_3 R51_4: library part CMP-0026796-1, "RES, 10.0 k, 0.1%, 0.063 W, 0402", Manufacturer="TT Electronics/IRC", Power_W=63mW, TempCo="10 ppm/C", Tolerance_%=0.1%, Value2=0.063W, Value_Code=10k0, ValueDisplayed=10.0k
R45_1 R45_2 R45_3 R45_4 R52_1 R52_2 R52_3 R52_4: library part CMP-0022204-4, "RES, 20.0 k, 1%, 0.1 W, AEC-Q200 Grade 0, 0603", Manufacturer=Vishay-Dale, Power_W=100mW, Supplier Part Number 1=541-20.0KHCT-ND, TempCo="100 ppm/C", Tolerance_%=1%, Value2=0.1W, Value_Code=20k0, ValueDisplayed=20.0k
R46_1 R46_2 R46_3 R46_4 R48_1 R48_2 R48_3 R48_4: library part CMP-0026367-2, "RES, 40.2 k, 1%, 0.063 W, AEC-Q200 Grade 0, 0402", Manufacturer=Vishay-Dale, Power_W=63mW, Supplier Part Number 1=541-40.2KLCT-ND, TempCo="100 ppm/C", Tolerance_%=1%, Value2=0.063W, Value_Code=40k2, ValueDisplayed=40.2k
R53: library part CMP-0026199-2, "RES, 255 k, 1%, 0.063 W, AEC-Q200 Grade 0, 0402", Manufacturer=Vishay-Dale, Power_W=63mW, Supplier Part Number 1=541-255KLCT-ND, TempCo="100 ppm/C", Tolerance_%=1%, Value2=0.063W, Value_Code=255k
R54: library part CMP-0026178-2, "RES, 22.1 k, 1%, 0.063 W, AEC-Q200 Grade 0, 0402", Manufacturer=Vishay-Dale, Power_W=63mW, Supplier Part Number 1=541-22.1KLCT-ND, TempCo="100 ppm/C", Tolerance_%=1%, Value2=0.063W, Value_Code=22k1, ValueDisplayed=22.1k
R55 R56: library part CMP-0094724-1, "Jumper 0.25W, 1/4W Chip Resistor 1206 (3216 Metric) - Thick Film", Digikey Part Number=541-4170-1-ND, Manufacturer=Vishay, Mouser Part Number=71-CRCW12060000Z0EAC, Operating Temperature Range="-55°C to +155°C", Power_W=250mW
R112: library part CMP-0026632-2, "RES, 0.22, 1%, 0.125 W, AEC-Q200 Grade 0, 0402", Manufacturer=Panasonic, Power_W=125mW, Supplier Part Number 1=P.22AKCT-ND, TempCo="250 ppm/C", Tolerance_%=1%, Value2=0.125W, Value_Code=R220, ValueDisplayed=0.22
R113: library part CMP-0022068-4, "RES, 15.8 k, 1%, 0.1 W, AEC-Q200 Grade 0, 0603", Manufacturer=Vishay-Dale, Power_W=100mW, Supplier Part Number 1=541-15.8KHCT-ND, TempCo="100 ppm/C", Tolerance_%=1%, Value2=0.1W, Value_Code=15k8, ValueDisplayed=15.8k
R118 R119 R120 R121 R143: library part CMP-0025951-3, "RES, 100, 1%, 0.063 W, AEC-Q200 Grade 0, 0402", Manufacturer=Vishay-Dale, Power_W=63mW, Supplier Part Number 1=541-100LCT-ND, TempCo="100 ppm/C", Tolerance_%=1%, Value2=0.063W, Value_Code=100R, ValueDisplayed=100
R122 R125: library part CMP-0026770-1, "RES, 1.00 k, 0.1%, 0.063 W, 0402", Manufacturer=Panasonic, Power_W=63mW, Supplier Part Number 1=P1.0KDCCT-ND, TempCo="25 ppm/C", Tolerance_%=0.1%, Value2=0.063W, Value_Code=1k00, ValueDisplayed=1.00k
R130 R132 R134 R135 R136 R137 R140 R141 R142 R144 R145 R146 R147 R148 R149 R150 R151 R152 R153 R154 R155 R158 R159 R160 R161 R162 R163: library part CMP-0026880-3, "RES, 22, 5%, 0.063 W, AEC-Q200 Grade 0, 0402", Manufacturer=Vishay-Dale, Power_W=63mW, Supplier Part Number 1=541-22JCT-ND, TempCo="200 ppm/C", Tolerance_%=5%, Value2=0.063W, Value_Code=22R0, ValueDisplayed=22
R164: library part CMP-0017667-3, "RES, 59.0, 1%, 0.25 W, AEC-Q200 Grade 0, 1206", Manufacturer=Panasonic, Power_W=250mW, Supplier Part Number 1=P59.0FCT-ND, TempCo="100 ppm/C", Tolerance_%=1%, Value2=0.25W, Value_Code=59R0, ValueDisplayed=59.0
SH-J1 SH-J2 SH-J3: library part CMP-0003761-2, "Shunt, 2.54mm, Gold, Black", Manufacturer="Wurth Elektronik", Supplier Part Number 1=732-2678-ND
T1 T2: library part CMP-0075010-2, "Terminal 70A Lug", Manufacturer=Panduit, Supplier Part Number 1=CXS70-14-C-ND
TP1_1 TP1_2 TP1_3 TP1_4: library part CMP-0055137-2, "Test Point, Miniature, Red, TH", Color=Red, Manufacturer="Keystone Electronics", Supplier Part Number 1=36-5000-ND
TP2_1 TP2_2 TP2_3 TP2_4 TP3 TP4 TP5 TP6 TP11 TP12 TP13: library part CMP-0055138-2, "Test Point, Miniature, Black, TH", Color=Black, Manufacturer="Keystone Electronics", Supplier Part Number 1=36-5001-ND
TP7 TP8 TP9 TP10: library part CMP-0003825-1, "1mm Test Point, SMT", Manufacturer=Any
U1_1 U1_2 U1_3 U1_4: library part CMP-0077837-1, "5-V Precision Surge Protection Clamp, DRV0006A (WSON-6)", Alternate Manufacturer="Texas Instruments"
U2_1 U2_2 U2_3 U2_4: library part CMP-0089361-1, "Dual Comparators", Input Bias Current=-0.0035uA, Input Offset Voltage=0.37mV, Manufacturer="Texas Instruments", Max Supply Voltage=36V, Min Supply Voltage=3V, Nominal Supply Current=400-550uA, Operating Temperature Range="-40°C to +85°C", Output Current Per Channel=21mA
U3_1 U3_2 U3_3 U3_4: library part CMP-0092668-1, "120-V Half-Bridge Driver with Negative Voltage Handling and Low Switching Losses", Manufacturer="Texas Instruments", Max Supply Voltage=16V, Min Supply Voltage=5.5V, Nominal Supply Current=0.3-2.2mA, Operating Temperature Range="-40°C to +125°C"
U4_1 U4_2 U4_3 U4_4: library part CMP-0096479-1, "Precision Current-Sense Amplifier Bi-Directional 1-Channel 200V/V 1.7V to 5.5V 6-Pin SC-70 T/R", Manufacturer="Texas Instruments", Max Supply Voltage=5.5V, Nominal Supply Current=48uA, Operating Temperature Range="-40°C to +125°C", Part Number=INA500BIDCKR
U5_1 U5_2 U5_3 U5_4: library part CMP-0121190-1, "Precision, Low-Power, Indirect Current Feedback Instrumentation Amplifier", Input Bias Current=0.006uA, Input Offset Voltage=0.05mV, Manufacturer="Texas Instruments", Max Dual Supply Voltage=18V, Max Supply Voltage=36V, Min Dual Supply Voltage=2.25V, Min Supply Voltage=4.5V, Nominal Supply Current=300uA, Operating Temperature Range="-40°C to +125°C", Output Current Per Channel=20mA, Voltage Gain=0.02-1V/mV
U6_1 U6_2 U6_3 U6_4: library part CMP-0038162-3, "Precision, 200-μA Supply Current, 36-V Supply Instrumentation Amplifier, DGK0008A (VSSOP-8)", Input Bias Current (+/-)(Max)(nA)=65, Manufacturer="Texas Instruments", Operating Temperature Range="-40 to 125 C", Quiescent Current (+/-)(Typ)(mA)=0.2, Rating=Catalog
U7_1 U7_2 U7_3 U7_4 U21: library part CMP-0100002-2, "5MHz, 15V/us High Slew-Rate, RRIO Op Amp, DGK0008A (VSSOP-8)", Alternate Manufacturer="Texas Instruments", Operating Temperature Range="-40 to 125 C", Rating=Catalog
U8: library part CMP-0093105-2, "Buck Converter, Adjustable, 4V-36V Input, 1-28V 1A Output, SOT23-6", Manufacturer="Texas Instruments", Max Supply Voltage=36V, Min Supply Voltage=4V, Nominal Supply Current=80uA, Operating Temperature Range="-40°C to +150°C", Output Voltage=1-28V, Switching Frequency=700kHz
U9: library part CMP-0095212-1, "Linear Voltage Regulator IC Positive Fixed 1 Output 300mA SOT-23-5", Digikey Part Number=296-TPS7A2018PDBVRCT-ND, Dropout Voltage=690mV, Manufacturer="Texas Instruments", Max Supply Voltage=6V, Min Supply Voltage=1.6V, Mouser Part Number=595-TPS7A2018PDBVR, Nominal Supply Current=6.5-2000uA, Operating Temperature Range="-40°C to +125°C", Output Voltage=1.8V
U10 U14: library part CMP-0036758-1, "Single Output LDO, 1 A, Fixed 5 V Output, 2 to 5.5 V Input, 4-pin SOT-223 (DCY), -40 to 125 degC, Green (RoHS & no Sb/Br)", Manufacturer="Texas Instruments", PartNumber=TLV1117-50IDCY
U11: library part CMP-0092532-1, "300-mA, Ultra-Low-Noise, Low-IQ, High PSRR LDO", Digikey Part Number=296-TPS7A2033PDBVRCT-ND, Dropout Voltage=145mV, Manufacturer="Texas Instruments", Max Supply Voltage=6V, Min Supply Voltage=1.6V, Mouser Part Number=595-TPS7A2033PDBVR, Nominal Supply Current=6.5uA, Operating Temperature Range="-40°C to +125°C", Output Voltage=3.3V
U12: library part CMP-0036866-2, "Single Output Low Noise LDO, 400 mA, Fixed 3.3 V Output, 1.7 to 5.5 V Input, with Reverse Current Protection, 5-pin SOT-23 (DBV), -40 to 85 degC, Green (RoHS & no Sb/Br)", Alternate Manufacturer="Texas Instruments", Alternate PartNumber=TPS73633DBVT, Rating=Catalog
U13: library part CMP-0072146-1, "Switched Capacitor Voltage Converter, 6-pin SOT-23", Manufacturer="Texas Instruments", PackageTopMarking=S03A*XTT, PartNumber=LM2664M6X/NOPB, PowerWise=N
U15: library part CMP-0124125-1, "16-Channel, 16-Bit, 1-MSPS Simultaneous-Sampling SAR ADC with Bipolar Inputs on a Single Supply", Manufacturer="Texas Instruments", Max Supply Voltage=5.25V, Min Supply Voltage=1.75V, Operating Temperature Range="-40°C to +125°C"
U16: library part CMP-0860945-1, "16-Channel, 16-Bit, 1-MSPS, Dual, Simultaneous Sampling ADC With Integrated Analog Front End, PZA0080A (LQFP-80)", Alternate Manufacturer="Texas Instruments"
U17: library part CMP-0078298-1, "Quad, 14-Bit, SPI Voltage Output DAC With Internal Reference, RTE0016D (WQFN-16)", Alternate Manufacturer="Texas Instruments"
U18: library part CMP-0032601-1, "Low Noise, Very Low Drift, Precision Voltage Reference, -40 to 125 degC, 8-pin SOIC (D), Green (RoHS & no Sb/Br)", Manufacturer="Texas Instruments", Rating=Catalog, Temp Coeff(Max)(ppm/ degree C)=3
U19: library part CMP-0120501-1, "Quad, 36-V, 1.2-MHz 3-mV offset voltage operational amplifier", Digikey Part Number=296-LM324BIPWRCT-ND, Input Bias Current=-0.01uA, Input Offset Voltage=0.6mV, Manufacturer="Texas Instruments", Max Dual Supply Voltage=18V, Max Supply Voltage=36V, Min Dual Supply Voltage=2.5V, Min Supply Voltage=5V, Mouser Part Number=595-LM324BIPWR, Nominal Supply Current=240-350uA, Operating Temperature Range="-40°C to +85°C", Output Current Per Channel=20mA, Voltage Gain=100V/mV
U20: library part CMP-0013250-3, "TMP235DCK, DCK0005A (SOT-5)", Manufacturer="Texas Instruments"
U22: library part CMP-0033359-4, "Isolated 5 V CAN Transceiver, DW0016B (SOIC-16)", Drivers Per Package=1, Manufacturer="Texas Instruments", Operating Temperature Range="-55 to 105 C", Rating=Catalog
ZZ1: library part CMP-0003616-3
ZZ2: library part CMP-0077236-1
ZZ3: library part CMP-0077237-1
ZZ4: library part CMP-0077238-1

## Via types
v1: diameter 20, hole 12.5, Top Layer to Bottom Layer, 1408 vias
v2: diameter 20, hole 12, Top Layer to Bottom Layer, tented both sides, 775 vias

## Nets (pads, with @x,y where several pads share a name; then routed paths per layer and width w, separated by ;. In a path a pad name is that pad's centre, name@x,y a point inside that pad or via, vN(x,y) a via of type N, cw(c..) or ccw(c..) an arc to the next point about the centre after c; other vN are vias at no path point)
1V8A: C47.1 C64.2 C65.2 C66.2 R57.2 U9.5 U15.30 U15.51 | length 3525.1
  Top Layer w7.87: R57.2@2026.81,1136.75 2324.14,1136.75 2358.38,1171 v2(2845,1171) ; v2(4014,1187.09) 4246.66,1187.09 4349.59,1084.16 4427.86,1084.16 v2(4428.38,1084.68) ; v2(4616.69,975.67) 4634.21,975.67 C66.2@4634.91,976.36 ; C66.2@4641.66,985.37 4642.02,985.74 U15.30@4686.52,985.74 ; U15.51@4995.57,985.74 5022.65,985.74 5026.59,981.8 5031.19,981.8 5035.8,977.19 5035.8,957.23 v2(5041.57,951.46)
  Top Layer w20: R57.2@2026.81,1136.75 2033.82,1129.74 C47.1@2033.82,1077.37 2033.82,1069.87 2035,1068.69 U9.5@2035,1024.77
  Power w7.87: v2(4616.69,975.67) 4632.16,975.67 4720.25,887.57 4829.95,887.57 4875.53,841.99 4893.6,841.99 4906.38,854.76 4906.38,856.02 4947.17,896.81 4947.17,904.33 4995.9,953.06 5039.97,953.06 v2(5041.57,951.46)
  Bottom Layer w7.87: v2(2845,1171) 2895.77,1221.77 3541.82,1221.77 3555.73,1207.86 3566.9,1207.86 3567.72,1207.04 3585.79,1207.04 3586.61,1207.86 3825.35,1207.86 3826.18,1207.04 3962.38,1207.04 3982.33,1187.09 v2(4014,1187.09) ; v2(4428.38,1084.68) 4450.97,1084.68 4556.05,979.61 v2@4620.63,979.61
  Bottom Layer w10: C64.2@5036.62,960.88 5037.16,960.88 5039.66,958.38 5039.66,953.37 v2(5041.57,951.46)
3V3A: C51.1 C89.1 C100.2 R58.2 U11.5 U19.4 U21.8 | length 2581.7
  Top Layer w7.87: C100.2@2148.12,470 U21.8@2203.5,470 ; v2(2482.36,606.67) 2482.36,783.64 2482.2,783.8 2482.2,803.3 2495.9,817.01 R58.2@2496.89,817.01 ; v2(4172.64,821.99) 4173.44,821.19 4173.44,767.4 U19.4@4174.23,766.6 C89.1@4174.23,696.84
  Power w10: v2(2482.36,606.67) 2998.44,606.67 3116.87,725.11 v2(3632.95,725.11)
  Bottom Layer w7.87: v2(2151.19,470) 2238,556.81 2348.52,556.81 2349.35,555.98 2367.42,555.98 2368.25,556.81 2432.5,556.81 2450.48,574.79 v2(2482.36,606.67) ; v2(3632.95,725.11) 3664.87,725.11 3780.44,840.67 4153.96,840.67 v2(4172.64,821.99)
3V3D: C59.1 C73.2 C74.2 C75.2 C76.2 C84.1 C85.2 C106.2 R61.1 R62.1 R64.2 R69.1 R70.2 R80.1 R81.1 R83.1 R90.1 R92.1 R108.2 U12.5 U15.34 U15.47 U16.49 U17.16 U22.1 | length 6557.4
  Top Layer w7.87: v2(2358.38,577.8) v2(2358.38,639.22) ; U17.16@3891.12,744.41 3891.42,744.71 3929.99,744.71 C84.1@3930.65,745.37 3935.15,745.37 3948.2,758.41 C85.2@3957.87,758.41 ; v2(4360.18,614.55) 4345.41,629.31 4337.81,629.31 4329.67,637.46 4329.67,684.65 4337.81,692.8 4349.04,692.8 4363.8,707.56 4363.8,729.86 ; R90.1@4363.8,797.95 4363.8,729.86 ; R81.1@4366.42,893.58 4351.66,878.81 4343.01,878.81 4305.76,841.56 4305.76,787.9 4363.8,729.86 ; v2(4698.44,870.81) 4699.04,870.81 4714.16,885.93 4719.73,885.93 4721.11,887.31 4732.88,887.31 4738.68,893.11 U15.34@4738.68,917.82 ; U16.49@4802.66,767.23 4802.92,766.97 4802.92,725.27 v2(4803.18,725.01) ; 4943.41,905.58 4943.41,894.23 4943.59,894.04 4943.59,888.91 C74.2@4955,877.5 ; R80.1@5294.7,748.07 R70.2@5294.7,808.55
  Top Layer w10: v2(2358.38,639.22) 2358.38,740.45 2348.27,750.56 2348.27,838.09 2358.76,848.58 2521.91,848.58 2541.67,828.81 2541.67,810.36 2561.44,790.59 2629.41,790.59 C59.1@2650,770 2666.81,770 2687.4,790.59 U12.5@2687.4,827.28 2735.63,827.28 R64.2@2740,822.91
  Power w7.87: v2(1773.07,939.07) 2072.92,639.22 v2(2358.38,639.22) ; v2(4360.18,614.55) 4392.44,646.81 4610.15,646.81 v2(4631.96,625) 4631.96,804.33 v2(4698.44,870.81) 4782.59,870.81 4823.78,829.61 4823.78,789.25 4803.18,768.65 v2(4803.18,725.01) ; 4823.78,826.24 4907.44,826.24 4955.89,874.69 v2@4955.89,875 ; v2(4956.2,875) 5083.13,748.07 v2(5288.14,748.07)
  Power w10: v2(2358.38,639.22) 2453.55,544.05 2768.54,544.05 2796.3,516.3 3074.43,516.3 3208.02,649.89 v2(3682.86,649.89) 3738.67,649.89 3853.78,765 v2@3965.5,765 ; v2@3967.25,771.16 4091.22,895.14 v2(4357.83,895.14)
  Bottom Layer w7.87: C106.2@2192.13,279.27 2193.51,280.64 2193.51,357.8 2200.32,364.61 2373.88,364.61 2478.41,469.14 2495.33,469.14 2496.14,468.33 2520.31,468.33 2540,488.01 2540,585.51 2494.98,630.52 2440.13,630.52 2387.4,577.8 v2(2358.38,577.8) ; v2(4698.44,870.81) 4708.59,870.81 C75.2@4710.17,872.39
  other v2: 3963.39,765
5VA: C30_1.2 C30_2.2 C30_3.2 C30_4.2 C46.1 C49.1 C50.1 C62.1 C67.1 C68.2 C69.2 C70.2 C71.2 C72.2 C82.2 C83.1 C86.1 C92.2 Q8_1.2 Q8_2.2 Q8_3.2 Q8_4.2 R14_1.2 R14_2.2 R14_3.2 R14_4.2 R15_1.2 R15_2.2 R15_3.2 R15_4.2 R59.1 R60.1 R63.2 U4_1.6 U4_2.6 U4_3.6 U4_4.6 U9.1 U10.2 U10.4 U11.1 U13.5 U15.26 U15.27 U15.56 U16.6 U16.15 U16.30 U16.71 U17.7 U18.2 U20.4 | length 21102.9
  Top Layer w7.87: v2(1450,4770) 1538.79,4858.79 1667.03,4858.79 v2(1725.82,4800) ; C49.1@2070.69,805.56 2078.19,805.56 2096.71,824.07 2180.54,824.07 C50.1@2185.39,819.22 2185.39,812.79 2191.45,806.72 2202.32,806.72 2225.06,783.99 2236.01,783.99 v2(2250,770) ; v2(2539.59,5088.21) R15_2.2@2616.81,5088.21 ; U13.5@2963.07,555 R63.2@3013.77,555 ; R63.2@3013.77,545.27 R63.2@3013.77,555 ; C62.1@3064.67,555 R63.2@3013.77,555 ; v2(3067.45,2993.73) U20.4@3067.45,2984.76 3109.57,2984.76 3119.25,2975.08 3123.19,2975.08 3130,2968.27 C92.2@3130,2964.33 ; v2(3702.22,694.72) 3709.72,694.72 3720,705 C83.1@3740,705 U17.7@3780.89,705.04 ; C72.2@4646.25,1026.5 4646.25,1027.7 v2(4651.53,1032.98) U15.27@4686.52,1032.98 U15.26@4686.52,1048.73 ; v2(4725.16,1409.09) 4725.52,1408.72 4725.52,1377.83 U16.15@4725.89,1377.47 ; U15.56@4995.57,1064.48 5028.02,1064.48 5036.84,1073.29 5045,1073.29 C71.2@5046.94,1071.35 5071.14,1071.35 5078.52,1078.73 C68.2@5086.02,1078.73 ; v2(5087.86,1084.68) 5086.02,1082.84 C68.2@5086.02,1078.73 ; U16.71@5146.16,1085.15 5144.28,1083.26 5090.56,1083.26 C68.2@5086.02,1078.73 ; v2(5232.11,1806.39) 5235.35,1806.39 5258.25,1829.28 5359.01,1829.28 5386.84,1801.45 v2(5493.91,1801.45) 5493.91,1803.89 5523.26,1833.24 5627.55,1833.24 5653.98,1806.81 v2(5768.23,1806.81) 5770.55,1809.13 5782.28,1809.13 5805.12,1831.97 5920.44,1831.97 5962.27,1790.13 v2(6059.26,1790.13) ; v2(5345.75,1111.83) 5345.75,1110.93 5390.74,1065.95 v2(5728.49,1065.95) ; Q8_4.2@5460.37,5094.5 5509.27,5094.5 5524.27,5079.5 R15_4.2@5525.25,5079.5 v2(5526.24,5079.5)
  Top Layer w10: v2(1833.82,1069.87) 1839.52,1064.17 1847.35,1064.17 1884.33,1027.18 R59.1@1885.32,1027.18 1886.52,1025.98 1931.43,1025.98 1934.45,1022.96 1983.31,1022.96 2016.27,990 v2(2085,990) ; v2(3255,4620) 3255,4644.47 3305,4694.47 v2(3305,4715) ; v2@4488.82,1085.15 U16.30@4535.93,1085.15 ; v2(4955.82,1347.76) 4956.01,1347.95 4956.01,1377.28 U16.6@4956.2,1377.47
  Top Layer w20: U10.4@2057.48,711.08 2070.69,724.29 C49.1@2070.69,805.56
  Power w7.87: v2(5087.86,1084.68) 5115.01,1111.83 v2(5345.75,1111.83)
  Power w10: v2(2085,990) 2100,975 2100,920 v2(2250,770) 2284.91,770 2492.98,561.93 2791.4,561.93 2808.33,545 v2(3069.36,545) 3198.13,673.77 3681.27,673.77 v2(3702.22,694.72) 3702.48,694.72 3920.77,913.01 4295.19,913.01 4470.35,1088.17 4479.26,1088.17 v2(4481.17,1090.08) ; v2(4651.53,1032.98) 4538.28,1032.98 v2(4481.17,1090.08) ; v2(4955.82,1347.76) 4804.58,1347.76 4783.49,1368.86 4783.49,1403.23 4777.63,1409.09 v2(4725.16,1409.09) 4704.92,1388.84 4704.92,1314.07 4694.65,1303.8 4694.65,1168.46 4665.23,1139.05 4530.14,1139.05 v2(4481.17,1090.08) ; v2@4958.43,1347.76 4994.56,1383.88 5223.84,1383.88 5367.53,1240.19 ; v2(5345.75,1111.83) 5367.53,1133.61 5367.53,1240.19 ; v2(5493.91,1801.45) 5493.91,1773.58 5367.53,1647.21 5367.53,1240.19
  Bottom Layer w7.87: v2(1450,4770) 1423.19,4743.19 1423.19,2434.69 1630,2227.88 1630,1414.28 1717.86,1326.42 1790.35,1326.42 1833.82,1282.96 v2(1833.82,1069.87) ; C67.1@4608.14,1028 4610.71,1030.57 C70.2@4649.11,1030.57 ; C69.2@5045.06,1068.19 5071.36,1068.19 v2(5087.86,1084.68) ; v2(5232.11,1806.39) 5232.11,1839.26 5236.08,1843.24 U4_4.6@5245.93,1843.24 ; v2(5493.91,1801.45) 5493.91,1834.33 5497.89,1838.3 U4_3.6@5507.73,1838.3 ; v2(5526.24,5079.5) 5549.92,5103.18 5945.71,5103.18 v2(5982.02,5139.5) ; v2(5728.49,1065.95) 5798.64,995.8 v2(5798.64,860.5) ; C30_2.2@5789.37,1806.81 5789.37,1828.36 5796.42,1835.41 U4_2.6@5806.26,1835.41 ; C30_1.2@6069.54,1796.94 6069.54,1823.01 6070.9,1824.36 6070.9,1828.16 6080.74,1828.16 U4_1.6@6083.61,1831.03
  Bottom Layer w10: v2(1184.35,5082.76) 1184.35,5117.86 1238.54,5172.05 1611.83,5172.05 1725.82,5058.06 v2(1725.82,4800) 1802.95,4722.87 1809.47,4722.87 1820.15,4712.2 2297.2,4712.2 2539.59,4954.59 v2(2539.59,5088.21) 2564.41,5113.03 2725.67,5113.03 2752.79,5140.15 v2(3067.45,5140.15) 3084.49,5140.15 3225,4999.64 3225,4795 3320,4700 3816.87,4700 3838.1,4678.77 3881.9,4678.77 4014.59,4811.46 v2(4014.59,5086.34) 4068.18,5139.93 v2(4542.65,5139.93) 4662.8,5019.78 4662.8,4844.14 4816.95,4690 5083.42,4690 5460.37,5066.95 v2(5460.37,5085.46) ; v2(3067.45,2993.73) 3067.45,4432.45 v2(3255,4620)
  other v2: 1641.13,5142.76
5VD: C55.1 C56.2 C58.1 C99.2 C101.2 C103.2 C104.2 J13.48 J13.84 J13.98 J13.112 J14.158 J14.180 U12.1 U12.3 U14.2 U14.4 | length 7182.3
  Top Layer w7.87: J14.180@1867.73,174.63 1870.66,171.7 1870.66,83.82 1903.47,51 v2(2239.61,51) 2214.18,76.43 J14.158@2214.18,174.63 ; v2(2823.52,51) 3281.65,509.13 C101.2@3736,509.13 ; J13.112@3733.72,175.5 3733.72,55.6 C99.2@3730.62,52.5 C99.2@3738.83,52.5 ; J13.98@3954.19,175.5 3954.19,101.73 3962.06,93.85 C103.2@3962.06,52.5 ; C103.2@3960.56,52.5 3959.06,51 v2(3740.34,51) ; C103.2@3966,52.5 3981.75,68.25 3981.75,69.21 3990.64,78.1 4155.93,78.1 4164.82,86.99 4164.82,89.55 4168.76,93.49 4168.76,169.6 J13.84@4174.66,175.5 ; C104.2@4867.58,56.7 J13.48@4867.58,175.5 ; C99.2@3738.83,52.5 v2(3740.34,51) ; C99.2@3738.83,52.5 v2(3740.34,51)
  Top Layer w10: U12.3@2612.6,935.55 2614.41,933.74 2614.41,925.87 2620.32,919.96 2620.32,909.64 2631.96,897.99 2668.04,897.99 2679.68,909.64 2679.68,919.96 2685.59,925.87 2685.59,933.74 U12.1@2687.4,935.55
  Top Layer w20: U14.2@2228.49,1002.44 U14.4@2474.56,1002.44
  Bottom Layer w7.87: v2(2493.4,994.64) 2493.4,991.35 2500.11,984.64 2500.11,819.92 2331.38,651.18 1938.18,651.18 1773.07,486.08 1773.07,325 2047.07,51 v2(2239.61,51) v2(3740.34,51) ; v2(3962.06,51) v2(4866.55,51)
